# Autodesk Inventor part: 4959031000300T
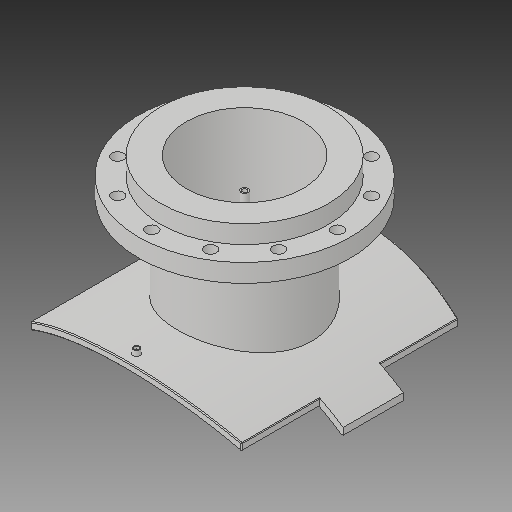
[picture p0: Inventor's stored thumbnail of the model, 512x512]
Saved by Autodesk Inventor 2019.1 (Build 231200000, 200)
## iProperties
Created: 2017-10
Part Number: 4959031000300T
Material: Generic
Description: PLASSON FLANGED BRANCH SADDLE 1000X300
Document SubType Name: Modeling
Designer: KIM
Mass: 2339.99 g
Surface Area: 3251.55 cm^2
Volume: 2339.99 cm^3
Density: 1 g/cm^3
Appearance: Default
Author: KIM
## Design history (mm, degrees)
derived "495904_495903.ipt"
feature "Solid1::495904_495903.ipt"
feature "Solid2::495904_495903.ipt"
tag "TaggingFeature1"
body "Solid1"
other parameters: "d1" = 15, "d2" = 464.4, "d4" = 0, "d6" = 132.5, "d7" = 0, "d12" = 525.6, "d13" = 14, "d14" = 238.5, "d16" = 5 deg, "d18" = 4, "d19" = 14, "d20" = 0, "d21" = 3, "d22" = 0, "d36" = 238.5, "d38" = 0, "d39" = 2, "d41" = 257, "d43" = 467, "d46" = 296, "d47" = 16, "d48" = 10.4, "d49" = 192.5, "d53" = 0, "d54" = 26, "d55" = 205, "d57" = 0, "d59" = 360 deg, "d63" = 0, "d66" = 275, "d67" = 15, "d68" = 137.5, "d70" = 0, "d71" = 2, "d72" = 516, "B_" = 516, "H_" = 275, "x_" = 15, "D_" = 16, "DN_" = 257, "D_1" = 467, "s_" = 26
